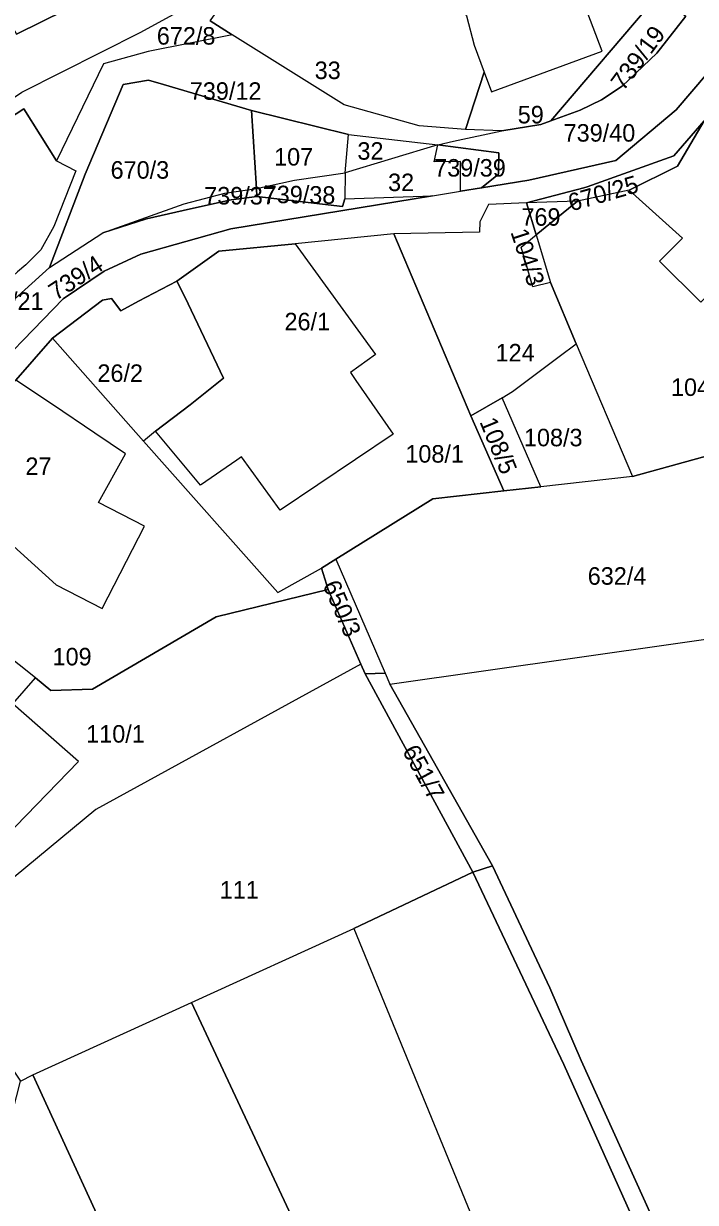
# Model space of a CAD drawing. Extents: x -629983 to -626385, y -1072828 to -1067897.
# Drawn here: x -627526.1 to -627411, y -1070665.2 to -1070463.2 of the extents above; entities that cross this region are included whole.
import ezdxf

# ---------------------------------------------------------------- set-up
doc = ezdxf.new("R2010")
doc.units = 0
for name, color, linetype in [('Parcela nároku', 7, 'Continuous'), ('Parcelní číslo', 7, 'Continuous'), ('Plocha PÚ', 7, 'Continuous'), ('Vnitřní obvod_šetřený', 7, 'Continuous')]:
    doc.layers.add(name, color=color, linetype=linetype)

msp = doc.modelspace()

# ---------------------------------------------------------------- linework, layer by layer
at = {"layer": 'Parcela nároku'}
for points in [[(-627532.81, -1070411.95), (-627539.12, -1070401.72), (-627556.41, -1070413.63), (-627549.89, -1070423.61), (-627547.92, -1070426.74), (-627550.24, -1070428.21), (-627547.59, -1070432.38), (-627544.83, -1070436.71), (-627530.63, -1070459.01), (-627527.27, -1070465.04), (-627510.48, -1070456.69), (-627495.48, -1070449.89), (-627497.86, -1070446.25), (-627503.29, -1070437.99), (-627506.5, -1070439.81), (-627509.42, -1070434.62), (-627520.07, -1070415.67), (-627527.83, -1070420.03)], [(-627433.3, -1070443.17), (-627435.92, -1070438.35), (-627443.05, -1070425.18), (-627447.9, -1070430.02), (-627448.84, -1070430.82), (-627464.23, -1070444), (-627462.02, -1070446.46), (-627455.66, -1070453.56), (-627455.61, -1070453.64), (-627450.18, -1070461.9), (-627448.86, -1070466.92), (-627447.15, -1070471.57), (-627445.92, -1070474.92), (-627426.96, -1070467.94), (-627430.02, -1070459.84), (-627430.61, -1070458.28), (-627419.52, -1070448.41), (-627426.7, -1070445), (-627431.94, -1070445.69)], [(-627486.45, -1070459.89), (-627481.47, -1070453.96), (-627471.87, -1070449.68), (-627468.6, -1070451.68), (-627466.14, -1070449.57), (-627464.43, -1070452.22), (-627461.8, -1070450.47), (-627463.51, -1070447.82), (-627462.02, -1070446.46), (-627455.66, -1070453.56), (-627455.61, -1070453.64), (-627450.18, -1070461.9), (-627448.86, -1070466.92), (-627447.15, -1070471.57), (-627450.35, -1070481.39), (-627458.28, -1070480.75), (-627471.12, -1070477.13), (-627490.34, -1070465.18), (-627494.07, -1070462.79), (-627490.34, -1070457.51)], [(-627450.35, -1070481.39), (-627447.15, -1070471.57), (-627445.92, -1070474.92), (-627426.96, -1070467.94), (-627430.02, -1070459.84), (-627430.61, -1070458.28), (-627419.52, -1070448.41), (-627417.42, -1070449.2), (-627415.31, -1070452.44), (-627418.77, -1070457.35), (-627417.42, -1070458.36), (-627435.72, -1070479.91), (-627437.43, -1070480.53), (-627444.16, -1070481.64)], [(-627417.42, -1070458.36), (-627412.62, -1070461.96), (-627417.57, -1070468.3), (-627423.53, -1070473.95), (-627427.09, -1070476.32), (-627430.7, -1070478.08), (-627435.72, -1070479.91)], [(-627515.51, -1070489.05), (-627521.61, -1070505.05), (-627512.49, -1070499.09), (-627498.57, -1070494.12), (-627491.57, -1070492.27), (-627486.15, -1070491.52), (-627487.02, -1070478.15), (-627502.09, -1070473.7), (-627504.66, -1070472.94), (-627509.01, -1070473.68)], [(-627542, -1070488.25), (-627526.02, -1070477.82), (-627520.44, -1070486.77), (-627517.11, -1070488.48), (-627520.87, -1070497.99), (-627523.07, -1070501.99), (-627525.66, -1070504.58), (-627527.07, -1070505.78), (-627530.44, -1070508.78), (-627536.47, -1070497.05)], [(-627470.42, -1070482.22), (-627487.02, -1070478.15), (-627486.15, -1070491.52), (-627479.62, -1070490.04), (-627470.95, -1070488.81)], [(-627414.7, -1070485.92), (-627409.45, -1070479.88), (-627414.04, -1070487.66), (-627422.32, -1070491.79), (-627431.19, -1070493.64), (-627439.89, -1070493.97), (-627430.1, -1070491.39), (-627429.53, -1070491.21)], [(-627392.97, -1070492.8), (-627389, -1070496.15), (-627390.12, -1070497.35), (-627396.31, -1070503.6), (-627399.65, -1070500.29), (-627402.31, -1070503.14), (-627410.02, -1070510.95), (-627417.12, -1070503.95), (-627413.21, -1070499.98), (-627422.32, -1070491.79), (-627414.04, -1070487.66), (-627409.45, -1070479.88)], [(-627470.95, -1070488.81), (-627470.42, -1070482.22), (-627455.07, -1070484)], [(-627470.95, -1070488.81), (-627471.02, -1070493.24), (-627456.03, -1070492.74), (-627451.19, -1070491.95), (-627451.23, -1070486.85), (-627455.73, -1070486.93), (-627455.07, -1070484)], [(-627455.07, -1070484), (-627444.63, -1070485.4), (-627444.71, -1070489.03), (-627447.63, -1070491.37), (-627451.19, -1070491.95), (-627451.23, -1070486.85), (-627455.73, -1070486.93)], [(-627486.15, -1070491.52), (-627479.62, -1070490.04), (-627470.95, -1070488.81), (-627471.02, -1070493.24), (-627471.41, -1070494.58), (-627486.11, -1070492.88)], [(-627498.57, -1070494.12), (-627491.57, -1070492.27), (-627486.15, -1070491.52), (-627486.11, -1070492.88), (-627490.48, -1070493.46), (-627497.44, -1070494.96), (-627505.02, -1070496.69), (-627512.49, -1070499.09)], [(-627396.31, -1070503.6), (-627399.65, -1070500.29), (-627402.31, -1070503.14), (-627410.02, -1070510.95), (-627417.12, -1070503.95), (-627413.21, -1070499.98), (-627422.32, -1070491.79), (-627431.19, -1070493.64), (-627438.26, -1070499.45), (-627435.82, -1070507.62), (-627431.38, -1070518.11), (-627421.76, -1070540.86), (-627392.8, -1070532.82), (-627373.54, -1070509.05), (-627374.46, -1070508.26), (-627389, -1070496.15), (-627390.12, -1070497.35)], [(-627435.82, -1070507.62), (-627438.8, -1070508.34), (-627440.81, -1070501.55), (-627438.26, -1070499.45), (-627439.89, -1070493.97), (-627446.39, -1070494.21), (-627447.92, -1070497.23), (-627447.95, -1070498.97), (-627462.65, -1070499.25), (-627449.45, -1070530.43), (-627444.05, -1070527.35), (-627442.32, -1070526.25), (-627434.29, -1070520.27), (-627431.38, -1070518.11)], [(-627431.19, -1070493.64), (-627439.89, -1070493.97), (-627438.26, -1070499.45)], [(-627489.53, -1070538.05), (-627495.74, -1070542.3), (-627503.44, -1070533.07), (-627505.54, -1070534.77), (-627482.52, -1070560.73), (-627475.03, -1070556.53), (-627472.55, -1070554.98), (-627455.97, -1070544.65), (-627443.78, -1070543.28), (-627449.45, -1070530.43), (-627462.65, -1070499.25), (-627479.55, -1070500.97), (-627465.78, -1070519.96), (-627470.03, -1070523.04), (-627469.13, -1070524.41), (-627462.77, -1070533.57), (-627482.09, -1070546.59), (-627488.71, -1070537.47)], [(-627469.13, -1070524.41), (-627462.77, -1070533.57), (-627482.09, -1070546.59), (-627488.71, -1070537.47), (-627489.53, -1070538.05), (-627495.74, -1070542.3), (-627503.44, -1070533.07), (-627497.54, -1070528.54), (-627491.81, -1070523.96), (-627498.45, -1070510.04), (-627499.82, -1070507.36), (-627492.6, -1070502.22), (-627479.55, -1070500.97), (-627465.78, -1070519.96), (-627470.03, -1070523.04)], [(-627438.26, -1070499.45), (-627435.82, -1070507.62), (-627438.8, -1070508.34), (-627440.81, -1070501.55)], [(-627511.02, -1070510.32), (-627509.41, -1070512.44), (-627506.35, -1070510.82), (-627499.82, -1070507.36), (-627498.45, -1070510.04), (-627491.81, -1070523.96), (-627497.54, -1070528.54), (-627503.44, -1070533.07), (-627505.54, -1070534.77), (-627521.12, -1070517.11), (-627512.53, -1070510.61)], [(-627550.19, -1070554.58), (-627541.26, -1070543.12), (-627540.27, -1070543.83), (-627530.29, -1070550.54), (-627520.48, -1070559.4), (-627512.61, -1070563.45), (-627505.35, -1070549.36), (-627513.22, -1070545.31), (-627508.58, -1070536.93), (-627513.85, -1070533.39), (-627521.11, -1070528.52), (-627527.39, -1070524.31), (-627521.12, -1070517.11), (-627505.54, -1070534.77), (-627482.52, -1070560.73), (-627475.03, -1070556.53), (-627473.88, -1070560.2), (-627493.09, -1070564.88), (-627514.26, -1070577.27), (-627521.4, -1070577.52), (-627524.03, -1070575.35), (-627548.69, -1070555.77)], [(-627444.05, -1070527.35), (-627442.32, -1070526.25), (-627434.29, -1070520.27), (-627431.38, -1070518.11), (-627421.76, -1070540.86), (-627437.46, -1070542.6)], [(-627529.07, -1070526.23), (-627532.54, -1070531.92), (-627540.27, -1070543.83), (-627530.29, -1070550.54), (-627520.48, -1070559.4), (-627512.61, -1070563.45), (-627505.35, -1070549.36), (-627513.22, -1070545.31), (-627508.58, -1070536.93), (-627513.85, -1070533.39), (-627521.11, -1070528.52), (-627527.39, -1070524.31)], [(-627437.46, -1070542.6), (-627444.05, -1070527.35), (-627449.45, -1070530.43), (-627443.78, -1070543.28)], [(-627455.97, -1070544.65), (-627472.55, -1070554.98), (-627464.1, -1070574.55), (-627463.29, -1070576.43), (-627398.36, -1070567.15), (-627370.14, -1070560.09), (-627392.8, -1070532.82), (-627421.76, -1070540.86), (-627437.46, -1070542.6), (-627443.78, -1070543.28)], [(-627548.69, -1070555.77), (-627550.19, -1070554.58), (-627556.38, -1070561.14), (-627554.98, -1070562.37), (-627562.6, -1070570.16), (-627567.25, -1070574.84), (-627569.95, -1070577.66), (-627564.5, -1070582.33), (-627545.76, -1070598.4), (-627542.27, -1070594.84), (-627531.04, -1070604.44), (-627516.67, -1070589.65), (-627527.92, -1070579.8), (-627524.03, -1070575.35)], [(-627472.55, -1070554.98), (-627464.1, -1070574.55), (-627467.55, -1070574.63), (-627468.28, -1070573), (-627473.88, -1070560.2), (-627475.03, -1070556.53)], [(-627493.09, -1070564.88), (-627473.88, -1070560.2), (-627468.28, -1070573), (-627513.68, -1070597.9), (-627542.07, -1070621.38), (-627562.59, -1070591.47), (-627566.78, -1070586.78), (-627569.24, -1070584.65), (-627573.36, -1070581.22), (-627569.95, -1070577.66), (-627564.5, -1070582.33), (-627545.76, -1070598.4), (-627542.27, -1070594.84), (-627531.04, -1070604.44), (-627516.67, -1070589.65), (-627527.92, -1070579.8), (-627524.03, -1070575.35), (-627521.4, -1070577.52), (-627514.26, -1070577.27)], [(-627360.53, -1070661.36), (-627310.09, -1070794.7), (-627345.73, -1070828.4), (-627360.76, -1070795.75), (-627366.36, -1070782.3), (-627384.74, -1070741.85), (-627400.99, -1070705.92), (-627417.12, -1070670.56), (-627430.56, -1070640.91), (-627435.89, -1070628.45), (-627445.75, -1070607.53), (-627463.29, -1070576.43), (-627398.36, -1070567.15)], [(-627467.55, -1070574.63), (-627468.28, -1070573), (-627513.68, -1070597.9), (-627542.07, -1070621.38), (-627526.57, -1070644.43), (-627524.44, -1070643.36), (-627497.28, -1070630.97), (-627469.47, -1070618.25), (-627449.08, -1070608.65)], [(-627467.55, -1070574.63), (-627464.1, -1070574.55), (-627463.29, -1070576.43), (-627445.75, -1070607.53), (-627449.08, -1070608.65)], [(-627430.56, -1070640.91), (-627435.89, -1070628.45), (-627445.75, -1070607.53), (-627449.08, -1070608.65), (-627433.51, -1070641.56), (-627413.29, -1070686.67), (-627397.03, -1070721.21), (-627387.43, -1070743.37), (-627368.97, -1070783.41), (-627363.03, -1070797.32), (-627351.95, -1070821.55), (-627347.85, -1070831.5), (-627345.73, -1070828.4), (-627360.76, -1070795.75), (-627366.36, -1070782.3), (-627384.74, -1070741.85), (-627400.99, -1070705.92), (-627417.12, -1070670.56)], [(-627413.29, -1070686.67), (-627433.51, -1070641.56), (-627449.08, -1070608.65), (-627469.47, -1070618.25), (-627445.72, -1070676.24), (-627429.68, -1070713.29), (-627412.5, -1070755.1), (-627387.43, -1070743.37), (-627397.03, -1070721.21)], [(-627445.72, -1070676.24), (-627429.68, -1070713.29), (-627412.5, -1070755.1), (-627437.6, -1070764.46), (-627447.75, -1070739.38), (-627476.84, -1070674.65), (-627497.28, -1070630.97), (-627469.47, -1070618.25)], [(-627428.4, -1070787.43), (-627420.85, -1070807.85), (-627416.32, -1070819.79), (-627432.25, -1070817.28), (-627436.93, -1070852.6), (-627440.33, -1070852.16), (-627444.51, -1070837.95), (-627450.33, -1070820.66), (-627459.42, -1070795.95), (-627467.69, -1070772.62), (-627485.16, -1070729.61), (-627494.54, -1070708.53), (-627524.44, -1070643.36), (-627497.28, -1070630.97), (-627476.84, -1070674.65), (-627447.75, -1070739.38), (-627437.6, -1070764.46)], [(-627526.57, -1070644.43), (-627524.44, -1070643.36), (-627494.54, -1070708.53), (-627485.16, -1070729.61), (-627467.69, -1070772.62), (-627459.42, -1070795.95), (-627450.33, -1070820.66), (-627444.51, -1070837.95), (-627440.33, -1070852.16), (-627482.19, -1070847.21), (-627487.27, -1070833.79), (-627496.33, -1070806.96), (-627518.25, -1070750.64), (-627541.19, -1070696.77), (-627538.48, -1070690.73)]]:
    msp.add_lwpolyline(points, close=True, dxfattribs=at)
for points in [[(-627673.05, -1070667.34), (-627668.64, -1070654.56), (-627665.13, -1070646.37), (-627658.25, -1070631.4), (-627656.03, -1070626.54), (-627638.9, -1070600.43), (-627632.14, -1070588.03), (-627621.09, -1070572.65), (-627613.29, -1070562.25), (-627601.8, -1070545.09), (-627596.37, -1070537.95), (-627595.51, -1070536.64), (-627592.06, -1070532.18), (-627582.07, -1070517.94), (-627580.74, -1070516.18), (-627560.93, -1070497.47), (-627556.12, -1070493.99), (-627551.42, -1070491.21), (-627543.28, -1070485.96), (-627536.7, -1070481.88), (-627526.35, -1070474.99), (-627505.98, -1070464.68), (-627477.81, -1070449.31)], [(-627494.07, -1070462.79), (-627490.34, -1070465.18), (-627504.72, -1070468.03), (-627512.37, -1070470.12), (-627520.44, -1070486.77), (-627526.02, -1070477.82), (-627542, -1070488.25), (-627536.47, -1070497.05), (-627530.44, -1070508.78), (-627531.96, -1070509.88), (-627536.72, -1070500.27), (-627543.67, -1070489.3), (-627546.86, -1070491.32), (-627550.7, -1070493.75), (-627551.42, -1070491.21), (-627543.28, -1070485.96), (-627536.7, -1070481.88), (-627526.35, -1070474.99), (-627505.98, -1070464.68), (-627477.81, -1070449.31)], [(-627616.87, -1070667.02), (-627601.41, -1070659.46), (-627592.65, -1070646.92), (-627588.86, -1070640.21), (-627593.43, -1070614.39), (-627588.8, -1070604.09), (-627582.29, -1070597.82), (-627581.64, -1070581.12), (-627578.43, -1070576.98), (-627576.18, -1070578.86), (-627544.29, -1070539.1), (-627534.71, -1070526.26), (-627519.29, -1070510.38), (-627512.24, -1070505.66), (-627505.99, -1070502.74), (-627490.53, -1070498.43), (-627456.03, -1070492.74), (-627451.19, -1070491.95), (-627447.63, -1070491.37), (-627439.53, -1070490.04), (-627424.62, -1070486.69), (-627414.27, -1070478.04), (-627406.21, -1070468.57), (-627399.6, -1070453.47)], [(-627399.6, -1070453.47), (-627406.21, -1070468.57), (-627414.27, -1070478.04), (-627424.62, -1070486.69), (-627439.53, -1070490.04), (-627447.63, -1070491.37), (-627444.71, -1070489.03), (-627444.63, -1070485.4), (-627455.07, -1070484), (-627452.42, -1070483.38), (-627444.16, -1070481.64), (-627437.43, -1070480.53), (-627435.72, -1070479.91), (-627430.7, -1070478.08), (-627427.09, -1070476.32), (-627423.53, -1070473.95), (-627417.57, -1070468.3), (-627412.62, -1070461.96)], [(-627510.48, -1070456.69), (-627527.27, -1070465.04)], [(-627528.88, -1070511.61), (-627521.61, -1070505.05), (-627515.51, -1070489.05), (-627509.01, -1070473.68), (-627504.66, -1070472.94), (-627502.09, -1070473.7), (-627487.02, -1070478.15), (-627470.42, -1070482.22), (-627455.07, -1070484), (-627452.42, -1070483.38), (-627444.16, -1070481.64), (-627450.35, -1070481.39), (-627458.28, -1070480.75), (-627471.12, -1070477.13), (-627490.34, -1070465.18), (-627504.72, -1070468.03), (-627512.37, -1070470.12), (-627520.44, -1070486.77), (-627517.11, -1070488.48), (-627520.87, -1070497.99), (-627523.07, -1070501.99), (-627525.66, -1070504.58), (-627527.07, -1070505.78)], [(-627409.45, -1070479.88), (-627414.7, -1070485.92), (-627429.53, -1070491.21), (-627430.1, -1070491.39), (-627439.89, -1070493.97), (-627446.39, -1070494.21), (-627447.92, -1070497.23), (-627447.95, -1070498.97), (-627462.65, -1070499.25), (-627479.55, -1070500.97), (-627492.6, -1070502.22), (-627499.82, -1070507.36), (-627506.35, -1070510.82), (-627509.41, -1070512.44), (-627511.02, -1070510.32), (-627512.53, -1070510.61), (-627521.12, -1070517.11), (-627527.39, -1070524.31)], [(-627528.88, -1070511.61), (-627521.61, -1070505.05), (-627512.49, -1070499.09), (-627505.02, -1070496.69), (-627497.44, -1070494.96), (-627490.48, -1070493.46), (-627486.11, -1070492.88), (-627471.41, -1070494.58), (-627471.02, -1070493.24), (-627456.03, -1070492.74), (-627490.53, -1070498.43), (-627505.99, -1070502.74), (-627512.24, -1070505.66), (-627519.29, -1070510.38), (-627534.71, -1070526.26)]]:
    msp.add_lwpolyline(points, dxfattribs=at)
at = {"layer": 'Plocha PÚ'}
msp.add_lwpolyline([(-627321.24, -1070458.86), (-627335.96, -1070472.15), (-627339.84, -1070477.13), (-627344.14, -1070479.15), (-627345.75, -1070479.75), (-627360.17, -1070494.95), (-627373.54, -1070509.05), (-627392.8, -1070532.82), (-627421.76, -1070540.86), (-627437.46, -1070542.6), (-627443.78, -1070543.28), (-627455.97, -1070544.65), (-627472.55, -1070554.98), (-627475.03, -1070556.53), (-627473.88, -1070560.2), (-627468.28, -1070573), (-627467.55, -1070574.63), (-627449.08, -1070608.65), (-627445.75, -1070607.53), (-627435.89, -1070628.45), (-627430.56, -1070640.91), (-627417.12, -1070670.56)], dxfattribs=at)
at = {"layer": 'Vnitřní obvod_šetřený'}
for p, q in [((-627392.8, -1070532.82), (-627421.76, -1070540.86)), ((-627421.76, -1070540.86), (-627437.46, -1070542.6)), ((-627443.78, -1070543.28), (-627455.97, -1070544.65)), ((-627437.46, -1070542.6), (-627443.78, -1070543.28)), ((-627455.97, -1070544.65), (-627472.55, -1070554.98)), ((-627472.55, -1070554.98), (-627475.03, -1070556.53)), ((-627475.03, -1070556.53), (-627473.88, -1070560.2)), ((-627473.88, -1070560.2), (-627468.28, -1070573)), ((-627468.28, -1070573), (-627467.55, -1070574.63)), ((-627467.55, -1070574.63), (-627449.08, -1070608.65)), ((-627449.08, -1070608.65), (-627445.75, -1070607.53)), ((-627445.75, -1070607.53), (-627435.89, -1070628.45)), ((-627435.89, -1070628.45), (-627430.56, -1070640.91)), ((-627430.56, -1070640.91), (-627417.12, -1070670.56))]:
    msp.add_line(p, q, dxfattribs=at)

# ---------------------------------------------------------------- texts
at = {"layer": 'Parcelní číslo'}
for s, p in [('672/8', (-627503.23, -1070466.84)), ('33', (-627476.19, -1070472.74)), ('739/12', (-627497.58, -1070476.29)), ('59', (-627441.41, -1070480.34)), ('739/40', (-627433.55, -1070483.46)), ('107', (-627483.14, -1070487.56)), ('32', (-627468.87, -1070486.56)), ('670/3', (-627511.15, -1070489.81)), ('739/39', (-627455.72, -1070489.45)), ('32', (-627463.62, -1070491.94)), ('739/37', (-627495.11, -1070494.23)), ('769', (-627440.78, -1070497.87)), ('739/21', (-627534.9, -1070512.29)), ('26/1', (-627481.36, -1070515.79)), ('124', (-627445.2, -1070521.12)), ('26/2', (-627513.41, -1070524.63)), ('104/1', (-627415.16, -1070527.03)), ('108/3', (-627440.35, -1070535.66)), ('108/1', (-627460.66, -1070538.46)), ('27', (-627525.74, -1070540.58)), ('632/4', (-627429.42, -1070559.38)), ('109', (-627521.09, -1070573.2)), ('110/1', (-627515.33, -1070586.43)), ('111', (-627492.46, -1070613.15))]:
    msp.add_text(s, height=3, dxfattribs=at).set_placement(p)
for s, rotation, p in [('739/19', 53.3161, (-627423.3, -1070474.92)), ('739/38', 359.2713, (-627484.94, -1070493.97)), ('670/25', 16.0625, (-627432.26, -1070495.45)), ('104/3', 287.9079, (-627442.68, -1070498.93)), ('739/4', 33.4522, (-627520.49, -1070510.78)), ('108/5', 292.3382, (-627448, -1070531.45)), ('650/3', 293.2702, (-627474.87, -1070559.41)), ('651/7', 298.679, (-627461.26, -1070587.85))]:
    msp.add_text(s, height=3, rotation=rotation, dxfattribs=at).set_placement(p)

doc.saveas('drawing.dxf')
